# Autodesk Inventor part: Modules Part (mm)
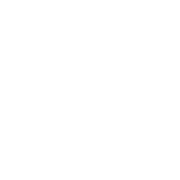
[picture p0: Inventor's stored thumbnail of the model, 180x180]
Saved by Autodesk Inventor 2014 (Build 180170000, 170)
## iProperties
Created: 2008-05
Part Number: Modules Part (mm)
Document SubType Name: Modeling
Designer: Wally
Density: 1 g/cm^3
Material: Generic
Appearance: Default
Author: Wally
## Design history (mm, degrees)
node "Sketch1"
